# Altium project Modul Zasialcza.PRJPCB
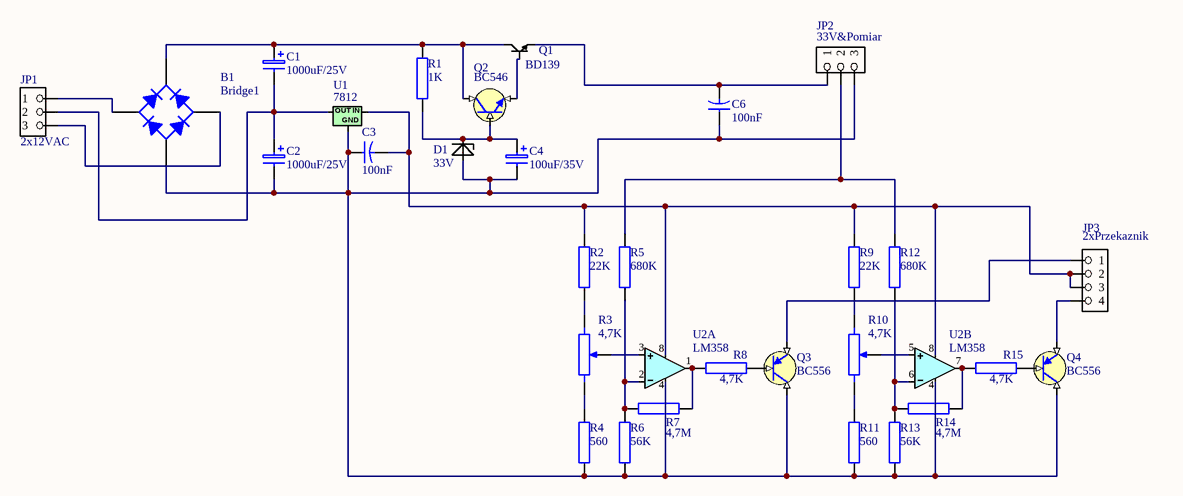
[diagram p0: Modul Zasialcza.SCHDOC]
1 sheet, 31 parts. Net scope: global (net labels, ports and power ports of the same name join across sheets).
Board file: Modul Zasilacza.PCBDOC

## Sheet Modul Zasialcza.SCHDOC
size B

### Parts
B1  Bridge1  [E-BIP-P4/D10]
C1  1000uF/25V  [C el./5mm]
C2  1000uF/25V  [C el./5mm]
C3  100nF  [C2]
C4  100uF/35V  [C el./2.5mm]
C6  100nF  [C2]
D1  33V  [D2]
JP1  2x12VAC  [JP3]
JP2  33V&Pomiar  [JP3]
JP3  2xPrzekaznik  [JP4]
Q1  BD139  [TO126V]
Q2  BC546  [TO92]
Q3  BC556  [TO92]
Q4  BC556  [TO92]
R1  1K  [AXIAL-0.3]
R2  22K  [AXIAL-0.3]
R3  4,7K  [PR5]
R4  560  [AXIAL-0.3]
R5  680K  [AXIAL-0.3]
R6  56K  [AXIAL-0.3]
R7  4,7M  [AXIAL-0.3]
R8  4,7K  [AXIAL-0.3]
R9  22K  [AXIAL-0.3]
R10  4,7K  [PR5]
R11  560  [AXIAL-0.3]
R12  680K  [AXIAL-0.3]
R13  56K  [AXIAL-0.3]
R14  4,7M  [AXIAL-0.3]
R15  4,7K  [AXIAL-0.3]
U1  7812  [TO220v]
U2  LM358  [U8]  (parts A,B of 2)

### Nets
NetB1_1: B1.1(A) B1.4(C) C2.2 C3.1 C4.2 C6.1 D1.1(K) JP1.3 JP2.3 Q3.3(C) Q4.3(C) R4.2 R6.2 R11.2 R13.2 U1.2(GND) U2.4(VCC-)
NetB1_2: B1.2(C) JP1.1
NetB1_3: B1.3(K) C1.1 Q1.3(B) Q2.3(C) R1.1
NetC1_2: C1.2 C2.1 JP1.2 U1.3(VIN)
NetC3_2: C3.2 JP3.2 JP3.3 R2.1 R9.1 U1.1(VOUT) U2.8(VCC+)
NetC4_1: C4.1 D1.2(A) Q2.2(B) R1.2
NetC6_2: C6.2 JP2.1 Q1.1(E)
NetJP2_2: JP2.2 R5.1 R12.1
NetJP3_1: JP3.1 Q3.1(E) R9.2 R10.1(TOP) R12.2 R13.1 R14.1 U2.6(IN2-)
NetJP3_4: JP3.4 Q4.1(E)
NetQ1_2: Q1.2(C) Q2.1(E)
NetQ3_2: Q3.2(B) R8.2
NetQ4_2: Q4.2(B) R15.2
NetR2_2: R2.2 R3.1(TOP)
NetR3_2: R3.2(BOT) R4.1
NetR3_3: R3.3(TAP) U2.3(IN1+)
NetR5_2: R5.2 R6.1 R7.1 U2.2(IN1-)
NetR7_2: R7.2 R8.1 U2.1(OUT1)
NetR10_2: R10.2(BOT) R11.1
NetR10_3: R10.3(TAP) U2.5(IN2+)
NetR14_2: R14.2 R15.1 U2.7(OUT)

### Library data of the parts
B1 = Bridge1: Full Wave Diode Bridge; pin to pad: 1>3 3>1; Manufacturer: Generic Components; Class I: Discrete; Class II: Rectifier - Bridge
C1 C2 C4 = CAP2: kONDENSATOR ELEKTROLITYCZNY
C3 = CAP: Condenstor
C6 = CAP: Condenstor; pin to pad: 1>2 2>1
D1 = BZX55C4V7: Dioda zenera
JP1 JP2 = JP3: ZLACZE 3 STYKOWE
JP3 = JP4: ZLACZE 4 STYKOWE
Q1 = BD139: Tranzystor; pin to pad: 1>3 3>1
Q2 = NPN: Tranzystor NPN
Q3 Q4 = PNP: Tranzystor PNP
R1 R2 R4-R9 R11-R15 = RES: Rezystor
R3 R10 = RPOT: Potencjometr
U1 = 78XX: @ 3-Terminal Positive Voltage Regulator; pin to pad: 1>3 3>1
U2 = LM358: Low-Noise JFET-Input Operational Amplifiers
